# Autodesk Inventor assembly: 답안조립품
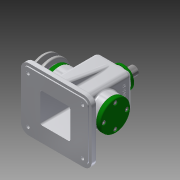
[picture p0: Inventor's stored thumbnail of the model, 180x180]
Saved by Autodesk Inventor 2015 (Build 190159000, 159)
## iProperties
Created: 2016-02
Part Number: 답안조립품
Document SubType Name: Assembly
Designer: Administrator
Author: Administrator
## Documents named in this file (19)
- C:\Users\Administrator\Desktop\460219V1015\답안조립품.iam
- C:\Users\Administrator\Desktop\460219V1015\본체.ipt
- C:\Users\Administrator\Desktop\460219V1015\V-벨트풀리.ipt
- C:\Users\Administrator\Desktop\460219V1015\고정핀.ipt
- C:\Users\Administrator\Desktop\460219V1015\뒤커버.ipt
- C:\Users\Administrator\Desktop\460219V1015\링크.ipt
- C:\Users\Administrator\Desktop\460219V1015\멈춤링 6 x 5.ipt
- C:\Users\Administrator\Desktop\460219V1015\멈춤링 15 x 1.ipt
- C:\Users\Administrator\Desktop\460219V1015\베어링 15 x 35 x 11.ipt
- C:\Users\Administrator\Desktop\460219V1015\볼트 M3 x 8.ipt
- C:\Users\Administrator\Desktop\460219V1015\볼트 M4 x 10.ipt
- C:\Users\Administrator\Desktop\460219V1015\볼트 M6 x 12.ipt
- C:\Users\Administrator\Desktop\460219V1015\상부부시.ipt
- C:\Users\Administrator\Desktop\460219V1015\슬라이드바.ipt
- C:\Users\Administrator\Desktop\460219V1015\앞커버.ipt
- C:\Users\Administrator\Desktop\460219V1015\오일실 15 25 7.ipt
- C:\Users\Administrator\Desktop\460219V1015\와셔.ipt
- C:\Users\Administrator\Desktop\460219V1015\키 5 x 5 x 14.ipt
- C:\Users\Administrator\Desktop\460219V1015\편심축.ipt
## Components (15 placed, 5 different names)
1. V-벨트풀리:1
2. 고정핀:1
3. ISO 4018 M6 x 12:1
4. ISO 4762 M4 x 10:2
5. ISO 4762 M4 x 10:3
6. ISO 4762 M4 x 10:4
7. ISO 4762 M4 x 10:5
8. ISO 4762 M4 x 10:6
9. ISO 4762 M4 x 10:7
10. ISO 4762 M4 x 10:8
11. ISO 4762 M4 x 10:9
12. ISO 4762 M3 x 8:1
13. ISO 4762 M3 x 8:2
14. ISO 4762 M3 x 8:3
15. ISO 4762 M3 x 8:4
